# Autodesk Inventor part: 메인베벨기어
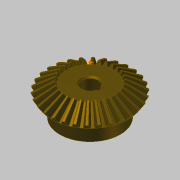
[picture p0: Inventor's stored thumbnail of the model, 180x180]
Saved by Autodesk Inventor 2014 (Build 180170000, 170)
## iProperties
Created: 2018-09
Part Number: 메인베벨기어
Material: 강철, 탄소
Document SubType Name: Modeling
Categories: <?xml version="1.0" encoding="UTF-16"?> <MemberInstance><Categories><FamilyTemplate><FamilyTemplateParameter ValueType="xs:double" Id="1" ObjectReferenceKey="da
Mass: 290.333 g
Surface Area: 107.709 cm^2
Volume: 36.8911 cm^3
Density: 7.87 g/cm^3
Appearance: 얼룩무늬
CustomPartVersion: 1
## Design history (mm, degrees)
node "맨 위 점"
node "메쉬 평면2"
sketch "톱니 본체 스케치"
  geometry: L1 (0, 0)-(28.669, -21.997); L2 (28.669, -21.997)-(31.109, -18.336); L3 (31.109, -18.336)-(0, 0); L4 (30, -20)-(0, 0); L5 (17.219, -13.212)-(18.685, -11.013); L6 (28.669, -21.997)-(17.219, -13.212); L7 (31.109, -18.336)-(18.685, -11.013); L8 (0, -39.387)-(0, 6.564) reference; L9 (0, -20)-(31.109, -20)
  constraints: 16 end point, 4 point on line, 3 perpendicular, 2 collinear, 1 horizontal alignment, 1 vertical alignment
  dimensions: "d0" = 60 diameter of L4.start L8 (= da_de); "d1" = 57.33744 diameter of L1.end L8 (= da_dfe); "d2" = 62.2188 diameter of L2.end L8 (= da_dae); "d3" = 14.4 distance between parallel lines of L2 L5 (= da_b); "d4" = 18.3359 vertical distance of L2.end L1.start (= da_ve)
revolve "톱니 본체" sketch "톱니 본체 스케치" stored, may be unused: angle "d5" = 90 deg
node "시작점"
node "톱니 평면"
sketch "시작 스케치"
  geometry: L1 (0, -23.505)-(0, 10.645) reference; L2 (-0.709, -2.928)-(0.709, -2.928); A1 r 19.188 centre (-19.457, -7.014) between (-0.709, -2.928) and (-3.232, 3.229); A2 r 19.188 centre (19.457, -7.014) between (3.232, 3.229) and (0.709, -2.928); A3 r 57.403 centre (0, -54.083) between (3.232, 3.229) and (-3.232, 3.229); 1 further point
  constraints: 6 point on circle, 3 centre point, 3 symmetric about line, 2 end point, 1 coincident, 1 perpendicular, 1 other
  dimensions: "d7" = 19.18795 radius of A1 (= fd_rr); "d8" = 19.45712 horizontal distance of point (0, -54.083) A1.centre (= fd_x); "d9" = 47.06905 vertical distance of point (0, -54.083) A1.centre (= fd_y); "d57" = 57.40327 radius of A3 (= 0.5 x fd_dva + 0.3 x da_he); "d58" = 51.15527 distance from line of A3.centre L2 (= 0.5 x fd_dva - 1.12 x da_he)
node "끝점"
  node "끝 평면"
sketch "3D 스케치 오른쪽"
  node "Helical Curve Right" dims "d65" = 229.90621 (computed from da_dm, da_delta, da_beta), "d66" = 31.5, "d67" = 60 (= da_de), "d68" = -9.82794 (= -da_delta), "d69" = 8.10972 (computed from fd_loft, da_delta)
node "끝 평면 오른쪽"
sketch "끝 스케치 오른쪽"
  geometry: L1 (0, -41.54)-(0, 13.178) reference; L2 (-0.422, -1.69)-(0.422, -1.69); A1 r 11.427 centre (-11.587, -4.123) between (-0.422, -1.69) and (-1.925, 1.977); A2 r 11.427 centre (11.587, -4.123) between (1.925, 1.977) and (0.422, -1.69); A3 r 34.184 centre (0, -32.153) between (1.925, 1.977) and (-1.925, 1.977); 1 further point
  constraints: 6 point on circle, 3 centre point, 3 symmetric about line, 2 end point, 1 coincident, 1 perpendicular, 1 other
  dimensions: "d70" = 11.58699 horizontal distance of A3.centre A1.centre (computed from fd_x, fd_ratio); "d71" = 28.03028 vertical distance of point (0, -32.153) A1.centre (computed from fd_y, fd_ratio); "d72" = 11.4267 radius of A1 (computed from fd_rr, fd_ratio); "d73" = 30.46369 distance from line of point (0, -32.153) L2 (computed from d58, fd_ratio); "d74" = 34.18446 radius of A3 (computed from d57, fd_ratio)
feature "로프트 오른쪽" sketch "끝 스케치 오른쪽" dims "d75" = 0, "d77" = 0, "d79" = 0, "d80" = 90 deg, "d85" = 20, "d92" = 90 deg, "d93" = 90 deg, "da_teethtype" = 0 [user parameter]
sketch "3D 스케치 왼쪽"
  node "Helical Curve Left" dims "d26" = 229.90621 (computed from da_dm, da_delta, da_beta), "d27" = 8.10972 (computed from fd_loft, da_delta), "d28" = 60 (= da_de), "d29" = -9.82794 (= -da_delta)
node "끝 평면 왼쪽"
sketch "끝 스케치 왼쪽" dims "d56" = 10.3728 (derived)
  geometry: L1 (0, -43.753)-(0, 15.405) reference; L2 (-0.422, -1.678)-(0.422, -1.678); A1 r 11.427 centre (-11.587, -4.111) between (-0.422, -1.678) and (-1.925, 1.988); A2 r 11.427 centre (11.587, -4.111) between (1.925, 1.988) and (0.422, -1.678); A3 r 34.184 centre (0, -32.142) between (1.925, 1.988) and (-1.925, 1.988); 2 further points; 1 other entity
  constraints: 6 point on circle, 3 centre point, 3 symmetric about line, 2 end point, 1 coincident, 2 other
  dimensions: "d30" = 11.4267 radius of A1 (computed from fd_rr, fd_ratio); "d31" = 11.58699 horizontal distance of point (0, -32.142) A1.centre (computed from fd_x, fd_ratio); "d32" = 28.03028 vertical distance of A1.centre point (0, -32.142) (computed from fd_y, fd_ratio); "d61" = 34.18446 radius of A3 (computed from d57, fd_ratio); "d62" = 30.46369 distance from line of point (0, -32.142) L2 (computed from d58, fd_ratio)
feature "로프트 왼쪽" sketch "끝 스케치 왼쪽" dims "d35" = 0, "d37" = 0, "d39" = 0, "d40" = 90 deg, "d84" = 10, "d90" = 90 deg, "d91" = 90 deg, "da_teethtype" = 0 [user parameter]
sketch "본체 스케치"
  geometry: L1 (0, -35.038)-(0, -19.531) reference; L2 (28.669, -21.997)-(17.219, -13.212) reference; L3 (17.219, -13.212)-(0, -13.212); L4 (28.669, -21.997)-(0, -21.997)
  constraints: 4 end point, 2 perpendicular, 2 point on line
revolve "본체 고정" sketch "본체 스케치" stored, may be unused: angle "d46" = 90 deg
feature "피치 지름" dims angle "d47" = 90 deg
sketch "스케치8"
  geometry: C1 r 22.5 at (0, 0); 1 further point
  constraints: 1 centre point, 1 coincident
  dimensions: "d94" = 45 diameter of C1
extrude "돌출1" join sketch "스케치8" distance "d95" = 13; taper "d96" = 0 deg
sketch "스케치9"
  geometry: 1 further point
hole "구멍1" sketch "스케치9" at (0, 0) diameter "d97" = 12; stored, may be unused: countersink angle "d101" = 90 deg, drill point angle "d103" = 118 deg; dims "d98" = 6, "d99" = 4, "d100" = 2, "d102" = 8
sketch "스케치10"
  geometry: L1 (5.657, 2)-(7.8, 2); L2 (7.8, 2)-(7.8, -2); L3 (7.8, -2)-(5.657, -2); A1 r 6 centre (0, 0) between (5.657, 2) and (5.657, -2) reference; 1 further point
  constraints: 6 end point, 2 parallel, 2 point on circle, 1 horizontal, 1 perpendicular
  dimensions: "d104" = 4 distance of L1.end L2.end; "d112" = 13.8 dimension on A1 L2
extrude "돌출2" cut sketch "스케치10" stored distance "d106" = 10; taper "d107" = 0 deg
chamfer "모따기1" distance "d108" = 1; stored, may be unused: second distance "d109" = 2, angle "d110" = 45 deg
fillet "모깎기1" dims "d111" = 2
body "Solid1"
feature "로프트" dims "d17" = 0, "d18" = 90 deg, "d19" = 0, "d20" = 90 deg, "d89" = 0, "da_teethtype" = 0 [user parameter]
pattern_circular "원형 패턴" dims angle "d22" = 360 deg, "d88" = 0, "da_teethtype" = 0 [user parameter]
pattern_circular "원형 패턴 오른쪽" dims angle "d82" = 360 deg, "da_teethtype" = 0 [user parameter]
pattern_circular "원형 패턴 왼쪽" dims angle "d42" = 360 deg, "da_teethtype" = 0 [user parameter]
sketch "끝 스케치"
  geometry: L1 (0, -15.359)-(0, 6.983) reference; L2 (-0.422, -1.69)-(0.422, -1.69); A1 r 11.427 centre (-11.587, -4.123) between (-0.422, -1.69) and (-1.925, 1.977); A2 r 11.427 centre (11.587, -4.123) between (1.925, 1.977) and (0.422, -1.69); A3 r 34.184 centre (0, -32.153) between (1.925, 1.977) and (-1.925, 1.977); 1 further point
  constraints: 6 point on circle, 3 centre point, 3 symmetric about line, 2 end point, 1 coincident, 1 other
  dimensions: "d12" = 11.4267 radius of A1 (computed from fd_rr, fd_ratio); "d15" = 11.58699 horizontal distance of A1.centre point (0, -32.153) (computed from fd_x, fd_ratio); "d16" = 28.03028 vertical distance of A1.centre point (0, -32.153) (computed from fd_y, fd_ratio); "d59" = 34.18446 radius of A3 (computed from d57, fd_ratio); "d60" = 30.46369 distance from line of A3.centre L2 (computed from d58, fd_ratio)
sketch "Sketch6"
  geometry: L1 (30, -20)-(0, 0) reference; L2 (0, -37.8)-(0, 6.3) reference
body "Srf1"
other parameters: "da_b" = 14.4 [user parameter; used in 2 equation terms], "da_de" = 60 [user parameter; used in 4 equation terms], "da_dae" = 62.2188 [user parameter; used in 2 equation terms], "da_dfe" = 57.33744 [user parameter; used in 1 equation term], "da_le" = 36.05551 [user parameter; used in 1 equation term], "da_omega" = 90 deg [user parameter; used in 1 equation term], "da_beta" = 0 [user parameter; used in 2 equation terms], "da_delta" = 9.82794 [user parameter; used in 8 equation terms], "da_alpha" = 20 deg [user parameter; used in 2 equation terms], "da_he" = 4.4 [user parameter; used in 4 equation terms], "da_ve" = 18.3359 [user parameter; used in 1 equation term], "fd_dv" = 108.16654 (computed from da_de, da_delta) [user parameter; used in 1 equation term], "fd_dva" = 112.16654 (computed from da_dae, da_delta) [user parameter; used in 3 equation terms], "fd_dvb" = 101.6433 (computed from fd_dv, da_alpha) [user parameter; used in 2 equation terms], "da_zv" = 540.83269 [user parameter; used in 1 equation term], "fd_loft" = 14.62 (= da_b + 0.05 x da_he) [user parameter; used in 4 equation terms], "fd_ratio" = 5.95514 (computed from da_le, fd_loft) [user parameter; used in 15 equation terms], "fd_rr" = 19.18795 (computed from fd_dd, fd_dvb) [user parameter; used in 6 equation terms], "fd_angle" = 0.29367 (computed from da_zv) [user parameter; used in 4 equation terms], "fd_x1" = 1.58802 (computed from da_dvw, fd_angle) [user parameter; used in 1 equation term], "fd_y1" = 54.05995 (computed from da_dvw, fd_angle) [user parameter; used in 1 equation term], "fd_x2" = 17.8691 (computed from fd_rr, fd_angle2, fd_angle) [user parameter; used in 1 equation term], "fd_y2" = 6.9909 (computed from fd_rr, fd_angle2, fd_angle) [user parameter; used in 1 equation term], "fd_x" = 19.45712 (= fd_x1 + fd_x2) [user parameter; used in 4 equation terms], "fd_y" = 47.06905 (= fd_y1 - fd_y2) [user parameter; used in 4 equation terms], "fd_angle2" = 3.43555 (computed from fd_dvb, fd_dd, da_alpha) [user parameter; used in 2 equation terms], "fd_dd" = 108.64654 (= fd_dva - 0.8 x da_he) [user parameter; used in 2 equation terms], "da_dvw" = 108.16654 [user parameter; used in 2 equation terms], "d11" = 14.62 (= fd_loft), "da_dm" = 48.01848 [user parameter; used in 2 equation terms], "da_x" = 0 [user parameter], "da_m" = 2 [user parameter], "d48" = 0, "d49" = 0, "d50" = 90 deg (= da_omega), "d51" = 6 deg (computed from da_z), "d52" = 0, "d53" = 0, "d54" = 0
